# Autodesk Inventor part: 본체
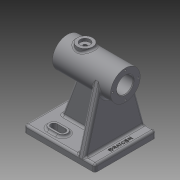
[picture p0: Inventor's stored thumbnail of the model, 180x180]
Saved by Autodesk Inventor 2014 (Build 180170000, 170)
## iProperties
Created: 2019-10
Part Number: 본체
Material: Generic
Document SubType Name: Modeling
Designer: kh
Density: 1 g/cm^3
Appearance: Default
Author: kh
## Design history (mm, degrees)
sketch "Sketch1"
  geometry: L1 (-50, 43)-(50, 43); L2 (50, 43)-(50, -43); L3 (50, -43)-(-50, -43); L4 (-50, -43)-(-50, 43); L5 (-50, 43)-(50, -43); L6 (50, 43)-(-50, -43); 1 further point
  constraints: 12 end point, 2 midpoint, 2 parallel, 1 horizontal, 1 perpendicular
  dimensions: "d0" = 100 distance of L1.start L1.end; "d1" = 86 distance of L1.end L2.end
extrude "Extrusion1" new body sketch "Sketch1" distance "d2" = 10; taper "d3" = 0 deg
sketch "Sketch2"
  geometry: L1 (0, 86)-(-32, 86); L2 (-32, 86)-(-32, 107); L3 (-32, 107)-(50, 107); L4 (50, 107)-(50, 86); L5 (50, 86)-(0, 86); L6 (-50, 0)-(50, 0) reference; L7 (50, 0)-(50, 10) reference; 3 further points
  constraints: 10 end point, 2 midpoint, 2 parallel, 1 collinear, 1 horizontal, 1 perpendicular, 1 vertical alignment
  dimensions: "d4" = 42 diameter of L3 L5; "d5" = 82 distance of L2.end L3.end; "d6" = 86 distance between parallel lines of L5 L6
revolve "Revolution1" sketch "Sketch2" stored, may be unused: angle "d7" = 90 deg
sketch "Sketch3"
  geometry: L1 (-32, 65)-(-32, 107) reference; L2 (50, 65)-(50, 107) reference; L3 (-32, 65)-(50, 65) reference; L4 (-32, 86)-(-32, 100.5); L5 (30, 100.5)-(30, 97.5); L6 (30, 97.5)-(50, 97.5); L7 (50, 97.5)-(50, 86); L8 (50, 86)-(-32, 86); L9 (-32, 100.5)-(30, 100.5); 1 further point
  constraints: 12 end point, 2 midpoint, 2 parallel, 2 perpendicular, 2 point on line
  dimensions: "d8" = 23 diameter of L6 L8; "d9" = 29 diameter of L9 L8; "d10" = 62 distance between parallel lines of L5 L1
revolve "Revolution2" sketch "Sketch3" stored, may be unused: angle "d11" = 90 deg
chamfer "Chamfer1" distance "d12" = 1; stored, may be unused: second distance "d13" = 2, angle "d14" = 45 deg
sketch "Sketch4"
  geometry: L1 (24, -27)-(12, -27); L2 (24, -20)-(12, -20); L3 (12, -34)-(24, -34); L4 (50, 43)-(50, -43) reference; L5 (-50, -43)-(-50, 43) reference; L6 (50, 0)-(-50, 0); A1 r 7 centre (24, -27) between (24, -34) and (24, -20); A2 r 7 centre (12, -27) between (12, -20) and (12, -34); 2 further points
  constraints: 10 end point, 4 point on circle, 4 tangent, 3 midpoint, 2 centre point, 1 horizontal, 1 parallel
  dimensions: "d15" = 12 distance of L3.start L3.end; "d16" = 14 distance between parallel lines of L2 L3; "d17" = 27 distance between parallel lines of L6 L1; "d18" = 26 distance from line of L3.end L4
extrude "Extrusion2" join sketch "Sketch4" distance "d19" = 3; taper "d20" = 0 deg
sketch "Sketch5"
  geometry: L1 (24, -27)-(12, -27); L2 (24, -22.5)-(12, -22.5); L3 (12, -31.5)-(24, -31.5); L4 (50, -43)-(50, 43) reference; A1 r 4.5 centre (24, -27) between (24, -31.5) and (24, -22.5); A2 r 4.5 centre (12, -27) between (12, -22.5) and (12, -31.5); 2 further points
  constraints: 8 end point, 4 point on circle, 4 tangent, 2 centre point, 1 horizontal, 1 midpoint, 1 parallel
  dimensions: "d21" = 12 distance of L3.start L3.end; "d22" = 9 distance between parallel lines of L2 L3; "d23" = 26 distance from line of L3.end L4; "d24" = 27 vertical distance of point (0, 0) point (18, -27)
extrude "Extrusion3" cut sketch "Sketch5" stored distance "d25" = 3; taper "d26" = 0 deg
fillet "Fillet1" dims "d27" = 3
mirror "Mirror1"
workplane "Work Plane1"
fillet "Fillet3" dims "d30" = 3
fillet "Fillet4" dims "d31" = 3
sketch "Sketch6"
  geometry: L1 (0, 86)-(7, 86) reference; L2 (7, 0)-(0, 0) reference; L3 (7.783, 85.896)-(91.48, 63.272); L4 (91.48, 22.728)-(7.783, 0.104); L5 (7.783, 85.896)-(7.783, 0.104); A1 r 21 centre (86, 43) between (91.48, 63.272) and (91.48, 22.728) reference; A2 r 3 centre (7, 83) between (10, 83) and (7, 86) reference; A3 r 3 centre (7, 3) between (7, 0) and (10, 3) reference; A4 r 21 centre (86, 43) between (91.48, 63.272) and (91.48, 22.728); 1 further point
  constraints: 6 end point, 6 point on circle, 6 tangent, 1 centre point, 1 perpendicular
extrude "Extrusion4" join sketch "Sketch6" distance "d32" = 10; taper "d33" = 0 deg
fillet "Fillet5" dims "d34" = 3
sketch "Sketch7"
  geometry: L1 (-47, 10)-(25.104, 10) reference; L2 (-35, 10)-(-20.243, 50.546); L3 (-50, 0)-(-50, 7) reference; 1 further point
  constraints: 2 end point, 1 point on line
  dimensions: "d36" = 15 distance from line of L2.start L3; "d37" = 70 deg angle of L1 L2
feature "Rib1" sketch "Sketch7" dims "d38" = 1, "d39" = 10, "d40" = 0, "d41" = 0, "d42" = 1, "d43" = 1
fillet "Fillet7" dims "d44" = 3
fillet "Fillet8" dims "d45" = 3
sketch "Sketch8" dims "d46" = 36
  geometry: C1 r 21 at (0, 0) reference; 3 further points
  constraints: 2 vertical alignment, 1 coincident, 2 other
hole "Hole1" sketch "Sketch8" at (0, 18) diameter "d47" = 2.459; stored, may be unused: countersink angle "d51" = 90 deg, drill point angle "d53" = 118 deg; dims "d48" = 8, "d49" = 4, "d50" = 2, "d52" = 10
pattern_circular "Circular Pattern1" dims angle "d55" = 360 deg
sketch "Sketch9" dims "d57" = 36
  geometry: C1 r 21 at (0, 0) reference; 3 further points
  constraints: 2 vertical alignment, 1 coincident, 2 other
hole "Hole2" sketch "Sketch9" at (0, 18) diameter "d58" = 2.459; stored, may be unused: countersink angle "d62" = 90 deg, drill point angle "d64" = 118 deg; dims "d59" = 8, "d60" = 4, "d61" = 2, "d63" = 10
pattern_circular "Circular Pattern2" dims angle "d66" = 360 deg
workplane "Work Plane2"
sketch "Sketch10"
  geometry: L1 (32, 21)-(32, -21) reference; L2 (32, 21)-(-50, 21) reference; C1 r 11 at (7, 0); 1 further point
  constraints: 1 centre point, 1 horizontal alignment
  dimensions: "d69" = 22 diameter of C1; "d70" = 25 distance from line of C1.centre L1
extrude "Extrusion5" join sketch "Sketch10" stored distance "d71" = 10; taper "d72" = 0 deg
sketch "Sketch11"
  geometry: C1 r 11 at (0, 0) reference; 2 further points
  constraints: 1 coincident
hole "Hole3" sketch "Sketch11" at (0, 0) diameter "d73" = 4.917; stored, may be unused: countersink angle "d77" = 90 deg, drill point angle "d79" = 118 deg; dims "d74" = 8, "d75" = 14, "d76" = 4, "d78" = 10
fillet "Fillet9" dims "d80" = 3
fillet "Fillet10" dims "d81" = 3
workplane "Work Plane3"
sketch "Sketch12"
  geometry: L1 (-40.598, 16.592)-(-40.598, -16.592); L2 (-40.598, -16.592)-(-45.402, -16.592); L3 (-45.402, -16.592)-(-45.402, 16.592); L4 (-45.402, 16.592)-(-40.598, 16.592); L5 (-40.598, 16.592)-(-45.402, -16.592); L6 (-40.598, -16.592)-(-45.402, 16.592); L7 (-50, 40)-(-50, -40) reference; L8 (47, 43)-(-47, 43) reference; 2 further points
  constraints: 4 end point, 1 midpoint, 2 other
  dimensions: "d83" = 7 distance from line of L7 point (-43, 0); "d84" = 43 distance from line of L8 point (-43, 0)
emboss "Emboss1" sketch "Sketch12" dims "d0" = 100, "d1" = 86, "d85" = 0.5, "d86" = 0
body "Solid1"
node "Projected Loop1"
other parameters: "d29" = -15, "d82" = 7
